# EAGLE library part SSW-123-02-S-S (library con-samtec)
THROUGH-HOLE .025" SQ POST SOCKET Source: Samtec SSW.pdf
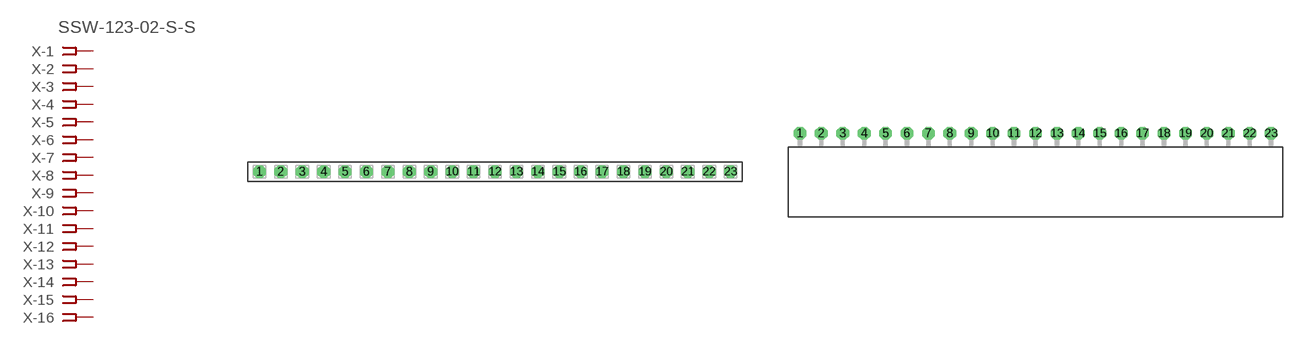
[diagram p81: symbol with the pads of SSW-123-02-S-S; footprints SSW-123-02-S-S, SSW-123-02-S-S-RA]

Designator prefix X; gates -1=FPINV -2=FPIN -3=FPIN -4=FPIN -5=FPIN -6=FPIN -7=FPIN -8=FPIN -9=FPIN -10=FPIN -11=FPIN -12=FPIN -13=FPIN -14=FPIN -15=FPIN -16=FPIN -17=FPIN -18=FPIN -19=FPIN -20=FPIN -21=FPIN -22=FPIN -23=FPIN

## SSW-123-02-S-S (MPN: SSW-123-02-S-S; OC_FARNELL: unknown; OC_NEWARK: 11P9692)  [SSW-123-02-S-S]
1  -1:1  pas
2  -2:1  pas
3  -3:1  pas
4  -4:1  pas
5  -5:1  pas
6  -6:1  pas
7  -7:1  pas
8  -8:1  pas
9  -9:1  pas
10  -10:1  pas
11  -11:1  pas
12  -12:1  pas
13  -13:1  pas
14  -14:1  pas
15  -15:1  pas
16  -16:1  pas
17  -17:1  pas
18  -18:1  pas
19  -19:1  pas
20  -20:1  pas
21  -21:1  pas
22  -22:1  pas
23  -23:1  pas

## SSW-123-02-S-S-RA (MPN: SSW-123-02-S-S-RA; OC_FARNELL: unknown; OC_NEWARK: 11P9693)  [SSW-123-02-S-S-RA]
Pads as for SSW-123-02-S-S

## Footprint SSW-123-02-S-S (pad centres in mm)
THROUGH-HOLE .025" SQ POST SOCKET Source: Samtec SSW.pdf
drill 1 pad 1.5 octagon: 1 -27.94,0; 2 -25.4,0; 3 -22.86,0; 4 -20.32,0; 5 -17.78,0; 6 -15.24,0; 7 -12.7,0; 8 -10.16,0; 9 -7.62,0; 10 -5.08,0; 11 -2.54,0; 12 0,0; 13 2.54,0; 14 5.08,0; 15 7.62,0; 16 10.16,0; 17 12.7,0; 18 15.24,0; 19 17.78,0; 20 20.32,0; 21 22.86,0; 22 25.4,0; 23 27.94,0

## Footprint SSW-123-02-S-S-RA (pad centres in mm)
THROUGH-HOLE .025" SQ POST SOCKET Source: Samtec SSW.pdf
drill 1 pad 1.5 octagon: 1 -27.94,1.524; 2 -25.4,1.524; 3 -22.86,1.524; 4 -20.32,1.524; 5 -17.78,1.524; 6 -15.24,1.524; 7 -12.7,1.524; 8 -10.16,1.524; 9 -7.62,1.524; 10 -5.08,1.524; 11 -2.54,1.524; 12 0,1.524; 13 2.54,1.524; 14 5.08,1.524; 15 7.62,1.524; 16 10.16,1.524; 17 12.7,1.524; 18 15.24,1.524; 19 17.78,1.524; 20 20.32,1.524; 21 22.86,1.524; 22 25.4,1.524; 23 27.94,1.524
